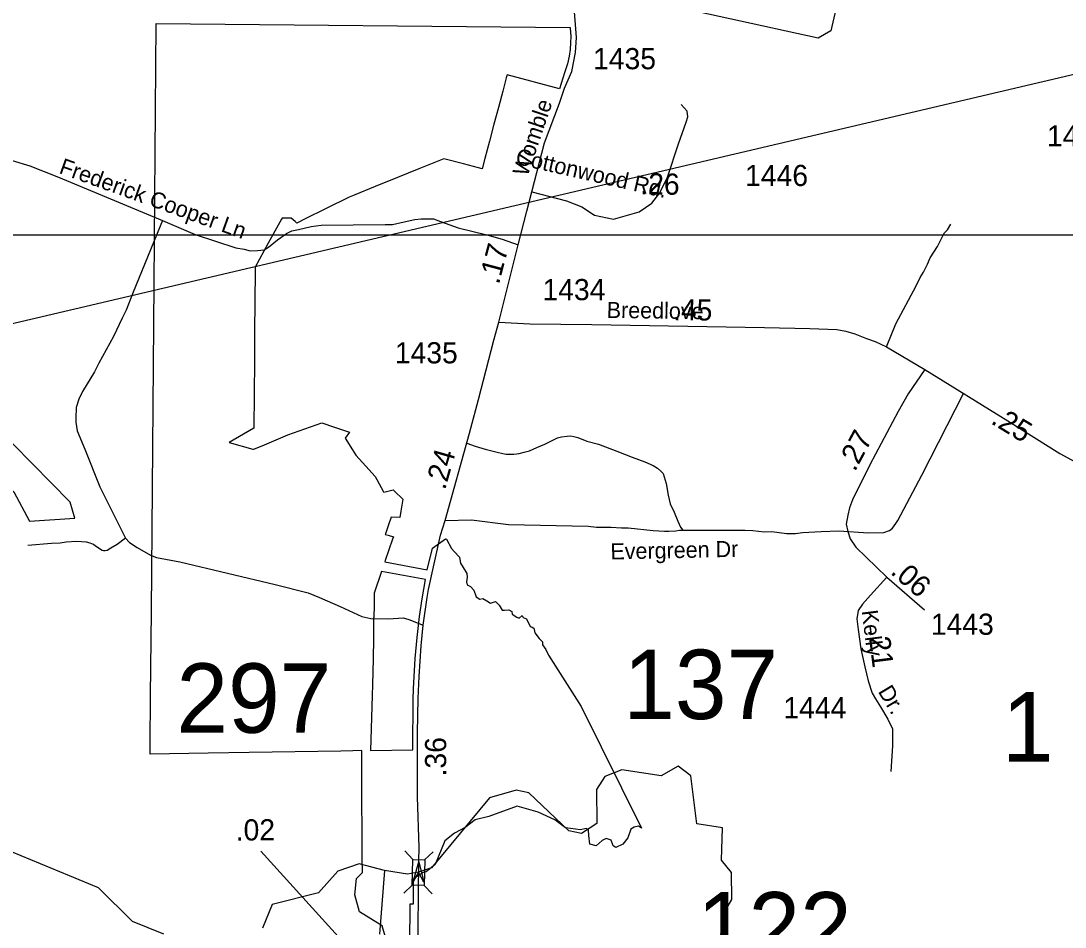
# Model space of a CAD drawing. Extents: x 2220236 to 2384410, y 720751 to 894131.
# Drawn here: x 2304345 to 2310514, y 814069 to 819421 of the extents above; entities that cross this region are included whole.
import ezdxf

# ---------------------------------------------------------------- set-up
doc = ezdxf.new("R2010")
doc.units = 0
for name, color, linetype in [('Exist Boundary Political City Limit New', 7, 'Continuous'), ('Exist Hydrographic Creek Single Shore', 7, 'Continuous'), ('Exist Hydrographic Lake Shore', 7, 'Continuous'), ('Exist Hydrographic Pond Under 1500 Sq Ft', 7, 'Continuous'), ('Exist Road Non-System Type 51', 7, 'Continuous'), ('Exist Road Non-System Type 51 Label', 7, 'Continuous'), ('Exist Road Primary US Mileage Hundredths English Label', 7, 'Continuous'), ('Exist Road Secondary Mileage Hundredths English Label', 7, 'Continuous'), ('Exist Road Secondary Structure Standard Bridge Attributed CELL', 7, 'Continuous'), ('Exist Road Secondary Structure Standard Bridge CELL', 7, 'Continuous'), ('Exist Road Secondary Structure Standard Bridge Number Label', 7, 'Continuous'), ('Exist Road Secondary Type 51 Attributed', 7, 'Continuous'), ('Exist Road Secondary Type 51 Label', 7, 'Continuous'), ('Exist Road Secondary Type 51 Number Label', 7, 'Continuous'), ('Exist Utilities Electrical Transmission Line', 7, 'Continuous'), ('Map Preparation Boundary City Limit Buffer Line', 7, 'Continuous'), ('Map Preparation Inset Cut Line', 7, 'Continuous')]:
    doc.layers.add(name, color=color, linetype=linetype)

msp = doc.modelspace()

# ---------------------------------------------------------------- linework, layer by layer
at = {"layer": 'Exist Boundary Political City Limit New'}
msp.add_lwpolyline([(2306496.2, 814015.8), (2306478.5, 814077.4), (2306345.8, 814158.9), (2306317, 814258.9), (2306327.2, 814356), (2306362.5, 814391.9), (2306362.2, 814474.1), (2306361.8, 814568), (2306360, 814883.1), (2306359.8, 815111.4), (2306305.8, 815110.3), (2306236, 815108.9), (2305694, 815100.2), (2305451.5, 815096.4), (2305107.8, 815090.9), (2305108.2, 815143.5), (2305111, 815434.5), (2305115.8, 815932.7), (2305132, 817870.4), (2305144.8, 819406.5), (2307589, 819382.9), (2307589.8, 819382.9), (2307590, 819379.1), (2307593.5, 819328.9), (2307592.5, 819293.5), (2307590.2, 819252.2), (2307583.5, 819212.9), (2307573.5, 819168.7), (2307557.5, 819114), (2307526.2, 819020.1), (2307217.2, 819102.4), (2307212.5, 819084.4), (2307191.5, 819005.8), (2307165.8, 818909.1), (2307139.5, 818810.6), (2307112.8, 818710.1), (2307086, 818609.6), (2307069.5, 818547.4), (2307048.5, 818553.1), (2306960.8, 818576.4), (2306844.5, 818607.3), (2306696.2, 818547.3), (2306570.5, 818496.4), (2306439, 818443.2), (2306314.2, 818392.7), (2306284.2, 818380.6), (2306145.5, 818311.8), (2306025.2, 818252), (2305975.8, 818227.5), (2305965.2, 818236.1), (2305941, 818255.8), (2305888, 818256.2), (2305885.2, 818251.3), (2305806.5, 818108.2), (2305755, 818014.8), (2305728.5, 817966.8), (2305728.5, 817944.9), (2305727, 817761.8), (2305725.8, 817587.6), (2305724.2, 817412.8), (2305722.8, 817216.5), (2305721.2, 817015.4), (2305574.5, 816931.6), (2305715.2, 816892.9), (2305721.2, 816891.2), (2305785.2, 816918.1), (2305922.2, 816975.9), (2306123.2, 817047.2), (2306198.5, 817021.4), (2306286.2, 816991.4), (2306261, 816956.4), (2306303.2, 816887.6), (2306324.8, 816856.2), (2306382.8, 816792.3), (2306438.2, 816731.1), (2306447.8, 816713.5), (2306487.8, 816639.8), (2306489.2, 816637.1), (2306528.2, 816647.4), (2306545, 816651.8), (2306552.2, 816644.6), (2306601.5, 816595.8), (2306590, 816526.2), (2306583.8, 816488.6), (2306532, 816491.2), (2306516.5, 816445.1), (2306498.5, 816392.1), (2306497.5, 816388.7), (2306514, 816383.8), (2306545.5, 816374.6), (2306540.5, 816360.5), (2306498, 816235.2), (2306495.2, 816226.4), (2306746, 816180.2), (2306776.2, 816306.5), (2306854, 816361.4), (2306859, 816360.2), (2306889.8, 816305.4), (2306905.5, 816287.9), (2306937.2, 816254.8), (2306937.5, 816239.8), (2306941.8, 816218.4), (2306957.8, 816192.4), (2306980.2, 816158), (2306981.2, 816136.6), (2306978.2, 816108.5), (2306981.5, 816089.8), (2307000.8, 816080.6), (2307020.2, 816059.9), (2307034.8, 816020.6), (2307056.8, 816006), (2307074.8, 816009.8), (2307098.8, 815996.4), (2307119, 815982.3), (2307149, 815992.4), (2307169.8, 815970.4), (2307188.2, 815941.4), (2307201.8, 815942), (2307227.8, 815943.1), (2307245.2, 815933.5), (2307248.2, 815916.5), (2307274.2, 815900.4), (2307288.2, 815892.8), (2307307.2, 815909.9), (2307312.5, 815897.9), (2307332, 815890), (2307354, 815845.4), (2307365, 815841.4), (2307376, 815834.1), (2307379, 815817.8), (2307381.2, 815806.2), (2307407, 815772.8), (2307426.2, 815754.8), (2307425.8, 815736.1), (2307446, 815708.4), (2307461.2, 815675.2), (2307655.2, 815371.8), (2308011.8, 814652.9), (2307994.2, 814664.4), (2307968, 814659.3), (2307948.5, 814648.5), (2307930.8, 814596.9), (2307902, 814559.7), (2307860.5, 814539.3), (2307844.5, 814549.1), (2307831.8, 814582.6), (2307802.8, 814593.4), (2307778.8, 814580.3), (2307743.8, 814550.1), (2307706.8, 814559.9), (2307700, 814610.3), (2307698.2, 814643.4), (2307684.8, 814651.2), (2307651.2, 814643.2), (2307562.5, 814655.3), (2307500.5, 814702.5), (2307402, 814748.1), (2307277, 814783.2), (2307109.8, 814721.7), (2307028.2, 814701.9), (2306970.5, 814657.8), (2306907.2, 814624), (2306849.2, 814577.8), (2306792.5, 814438.4), (2306738.8, 814395.9), (2306722.5, 814392.3), (2306662.8, 814353.2), (2306663.2, 814204.9), (2306643.2, 814204.9), (2306643.2, 814119.3), (2306633.8, 813771.7)], dxfattribs=at)
msp.add_lwpolyline([(2306420.5, 815437.1), (2306410.2, 815112.2), (2306659.8, 815116.2), (2306662.5, 815415.6), (2306664, 815475.8), (2306673.8, 815655.4), (2306686.2, 815780), (2306701, 815904.1), (2306714.8, 816007.9), (2306735.2, 816121.6), (2306476, 816169), (2306433, 816041.8), (2306432.8, 816034.6), (2306431.2, 815968.8), (2306429.5, 815899.4), (2306429.2, 815892.9), (2306428.8, 815872.6), (2306428.5, 815774.4), (2306425.5, 815654.4), (2306422, 815500.4)], close=True, dxfattribs=at)
at = {"layer": 'Exist Hydrographic Creek Single Shore'}
for points in [[(2308479.6, 814025), (2308495.6, 814147.1), (2308544.6, 814231.2), (2308542.5, 814391.9), (2308483.5, 814465), (2308489.4, 814655.6), (2308339.5, 814678.9), (2308303.4, 814963), (2308227.5, 815019), (2308128.5, 814962.4), (2307894.5, 814998.8), (2307795.5, 814958.6), (2307746.5, 814881.1), (2307748.5, 814681), (2307657.5, 814621.5), (2307582.4, 814638.1), (2307346.4, 814861.5), (2307271.4, 814878.1), (2307113.5, 814832.3), (2306771.4, 814418.4), (2306694.9, 814392.9), (2306628.2, 814381.9), (2306493.4, 814403.3)], [(2305189.5, 814028.3), (2305005.3, 814102.8), (2304803.3, 814301.4), (2304058.4, 814608.9)], [(2306493.4, 814403.3), (2306343.5, 814443.1), (2306218.4, 814398.6), (2306103.4, 814272.5), (2305829.4, 814202.2), (2305772.4, 814062)], [(2306493.4, 814403.3), (2306464.5, 814027.9)]]:
    msp.add_lwpolyline(points, dxfattribs=at)
at = {"layer": 'Exist Hydrographic Lake Shore'}
msp.add_lwpolyline([(2309185.6, 819603.6), (2309130.4, 819361.8), (2309055.6, 819319.4), (2308012.4, 819549), (2307605.6, 819568.2), (2307220.5, 819615.2), (2307069.4, 819664.8), (2306825.4, 819904.2)], dxfattribs=at)
at = {"layer": 'Exist Hydrographic Pond Under 1500 Sq Ft'}
msp.add_lwpolyline([(2304395.6, 816466.7), (2304662.8, 816484.1), (2304636.8, 816578.2), (2304299.7, 816922.2), (2304106.7, 817012.8), (2303982.6, 816984.7), (2303983.7, 816902.7), (2304302.7, 816640.1), (2304395.6, 816466.7)], dxfattribs=at)
at = {"layer": 'Exist Road Non-System Type 51'}
msp.add_line((2309494.3, 815139), (2309485.5, 814988.4), dxfattribs=at)
for points in [[(2304293, 818596.7), (2304397.1, 818565.7), (2304566.7, 818497.5), (2305182.2, 818243.4)], [(2305182.2, 818243.4), (2305009, 817819.3), (2304966.1, 817712.9), (2304942.6, 817666.6), (2304891.8, 817558.1), (2304805.4, 817399.3), (2304780.1, 817349), (2304709.4, 817232.3), (2304687.8, 817188.2), (2304672.5, 817138), (2304669, 817076), (2304669.4, 817052), (2304677.9, 817000.1), (2304723.1, 816892.6), (2304811.4, 816669.7), (2304962.5, 816365.4)], [(2305182.2, 818243.4), (2305373.8, 818159.3), (2305615.5, 818081.5), (2305664.8, 818073), (2305700, 818063.2), (2305743.6, 818064.6), (2305781.6, 818070.2), (2305808.3, 818084.3), (2305861.8, 818127.9), (2305913.8, 818165.9), (2305946.2, 818181.4), (2305984.2, 818189.9), (2306060.3, 818206.4), (2306118.2, 818215.2), (2306497.7, 818218), (2306539.9, 818218), (2306608.8, 818234.9), (2306672.2, 818249), (2306710.1, 818253.2), (2306745.3, 818253.2), (2306781.9, 818251.8), (2306824.1, 818236.3), (2306928, 818199.8), (2307097.4, 818158.3), (2307188.7, 818132.6), (2307282.1, 818099.1)], [(2309459.3, 817497.2), (2309514.8, 817631.9), (2309634.5, 817857), (2309657.9, 817905.4), (2309677.6, 817937.6), (2309700.9, 817983.8), (2309716.6, 818021.8), (2309759.9, 818088.4), (2309794.8, 818156.7), (2309801, 818168.7), (2309818.9, 818186.9), (2309838.5, 818221.1)], [(2308256.6, 816412.7), (2308624.3, 816412.9), (2308670.4, 816411.4), (2308736.5, 816404.1), (2308781.9, 816405.4), (2308867.7, 816394.2), (2308921.1, 816394.2), (2308963.4, 816399.8), (2309073.3, 816406.4), (2309177.2, 816409.6), (2309353.1, 816397), (2309443.1, 816399.8), (2309476.9, 816411.1), (2309495.2, 816425.1), (2309513.5, 816453.3), (2309526.1, 816471.6), (2309668.2, 816737.7), (2309915.1, 817225.5)], [(2306978.8, 816926.6), (2307028.8, 816909.4), (2307087.9, 816892.5), (2307159.7, 816874.2), (2307192, 816865.8), (2307211.7, 816863), (2307235.6, 816861.6), (2307258.1, 816863), (2307289.1, 816867.2), (2307318.6, 816874.2), (2307349.6, 816882.7), (2307393.2, 816902.4), (2307441, 816922.1), (2307515.6, 816958.7), (2307539.5, 816965.7), (2307571.9, 816968.6), (2307594.4, 816970), (2307611.3, 816967.2), (2307635.2, 816960.1), (2307688.7, 816939), (2307757.6, 816922.1), (2307865.9, 816879.9), (2307956, 816844.7), (2308032, 816817.9), (2308081.2, 816795.4), (2308106.5, 816779.9), (2308126.2, 816761.6), (2308138.9, 816748.9), (2308145.9, 816729.2), (2308157.2, 816689.8), (2308169.8, 816620.8), (2308181.1, 816568.7), (2308205, 816519.5), (2308226.1, 816466), (2308243, 816430.8), (2308256.6, 816412.7)], [(2306851.5, 816471.6), (2307006.3, 816474.4), (2307225.8, 816447.7), (2307696.6, 816436.8), (2307746.4, 816430.8), (2307832.2, 816430.8), (2307894.1, 816426.5), (2307933.5, 816426.5), (2308081.2, 816412.5), (2308147.3, 816406.8), (2308174.1, 816408.2), (2308214.7, 816410.4), (2308236.6, 816412.7), (2308256.6, 816412.7)], [(2304962.5, 816365.4), (2304913, 816328.9), (2304877.3, 816306.5), (2304855.4, 816294.4), (2304843.4, 816292.3), (2304833.4, 816292.1), (2304825.4, 816293.9), (2304785.1, 816319.5), (2304773.1, 816329.4), (2304755, 816337.3), (2304732.9, 816343), (2304673, 816346.3), (2304613, 816341.7), (2304577.1, 816337.2), (2304525.2, 816334.7), (2304385.2, 816323.2)], [(2304962.5, 816365.4), (2304986.8, 816339.7), (2305031.1, 816312.1), (2305111.6, 816265), (2305145.8, 816251.4), (2305284.9, 816227.3), (2305847.1, 816093), (2306041.8, 816042.9), (2306109.4, 816016.2), (2306230.4, 815962.7), (2306282.4, 815938.7), (2306359.8, 815903.5), (2306413.3, 815890.9), (2306518.8, 815889.4), (2306603.2, 815896.5), (2306637, 815885.2), (2306721.4, 815852.6)]]:
    msp.add_lwpolyline(points, dxfattribs=at)
at = {"layer": 'Exist Road Primary US Mileage Hundredths English Label'}
msp.add_line((2306550, 813648.7), (2305763.2, 814518), dxfattribs=at)
at = {"layer": 'Exist Road Secondary Structure Standard Bridge Attributed CELL'}
msp.add_lwpolyline([(2306661.8, 814337), (2306696.7, 814453.8), (2306724.9, 814335.2), (2306694.9, 814392.9)], close=True, dxfattribs=at)
at = {"layer": 'Exist Road Secondary Structure Standard Bridge CELL'}
for p, q in [((2306661.3, 814468.5), (2306613.9, 814518.7)), ((2306730.2, 814466.6), (2306780.4, 814514)), ((2306606.6, 814270.1), (2306656.7, 814317.5)), ((2306774.7, 814265.4), (2306727.3, 814315.5))]:
    msp.add_line(p, q, dxfattribs=at)
msp.add_lwpolyline([(2306656.7, 814317.5), (2306660.9, 814468.5), (2306731.5, 814466.6), (2306727.3, 814315.5)], close=True, dxfattribs=at)
at = {"layer": 'Exist Road Secondary Type 51 Attributed'}
msp.add_line((2309461.4, 816135), (2309683.1, 815942.1), dxfattribs=at)
for points in [[(2307363.3, 818412.5), (2307439.3, 818700.9), (2307526.8, 818935), (2307557.5, 819024.8), (2307599.1, 819123.5), (2307621, 819235.2), (2307627.6, 819322.9), (2307612.2, 819526.7), (2307555.8, 819875.2)], [(2307363.3, 818412.5), (2307568.6, 818357.9), (2307658.3, 818323.6), (2307734.8, 818273.5), (2307845.6, 818249.8), (2307998.7, 818294.6), (2308072.5, 818344.7), (2308120, 818405.4), (2308164.9, 818497.7), (2308230.8, 818695.6), (2308275.7, 818822.3), (2308286.2, 818853.9), (2308280.9, 818888.2), (2308246.6, 818927.8)], [(2307169.5, 817641.5), (2307282.1, 818099.1), (2307334.8, 818298.1), (2307363.3, 818412.5)], [(2306696.3, 814459.1), (2306697.4, 814539), (2306688.2, 814838.7), (2306687.6, 815216.5), (2306691.2, 815418.5), (2306698.2, 815549.5), (2306710.6, 815730.5), (2306721.4, 815852.6), (2306745.3, 816016.2), (2306753.8, 816062.6), (2306824.9, 816383.1), (2306851.5, 816471.6), (2306995, 816985.5), (2307048.5, 817185.4), (2307140, 817535.9), (2307169.5, 817641.5)], [(2307169.5, 817641.5), (2307352.4, 817631.7), (2307718.9, 817628.1), (2308738.9, 817611.2), (2309006.3, 817605.6), (2309165.5, 817598.2), (2309219.5, 817588.8), (2309271.6, 817573.3), (2309341.9, 817546), (2309391.8, 817528.2), (2309459.3, 817497.2), (2309685.8, 817362)], [(2309685.8, 817362), (2309586.7, 817219.6), (2309528.9, 817113.5), (2309360.2, 816800.2), (2309258.9, 816592.9), (2309239.6, 816544.7), (2309230, 816501.3), (2309220.4, 816448.3), (2309230, 816404.9), (2309244.5, 816361.5), (2309278.2, 816313.3), (2309461.4, 816135)], [(2309685.8, 817362), (2310176.9, 817060), (2310482.6, 816867.3), (2310621.6, 816791.1), (2310739.6, 816720.2), (2310772.9, 816698.5), (2310829.7, 816654.3)], [(2309461.4, 816135), (2309365, 816030.4), (2309316.8, 815977.3), (2309292.7, 815938.7), (2309283, 815890.5), (2309292.7, 815827.8), (2309307.1, 815712), (2309331.2, 815605.9), (2309350.5, 815523.9), (2309374.6, 815451.5), (2309393.9, 815417.7), (2309422.8, 815369.5), (2309466.2, 815297.1), (2309495.1, 815239.2), (2309495.1, 815152.4), (2309494.3, 815139)], [(2306666.2, 813531.8), (2306682.7, 813739), (2306691.2, 813938.9), (2306691.2, 814064.2), (2306696.3, 814459.1)]]:
    msp.add_lwpolyline(points, dxfattribs=at)
at = {"layer": 'Exist Utilities Electrical Transmission Line'}
msp.add_lwpolyline([(2295924, 816056.1), (2298361.2, 816772.1), (2303102.7, 817354.9), (2310903.7, 819186.1), (2317962.4, 822463)], dxfattribs=at)
at = {"layer": 'Map Preparation Boundary City Limit Buffer Line'}
msp.add_lwpolyline([(2306496.2, 814015.8), (2306478.5, 814077.4), (2306345.8, 814158.9), (2306317, 814258.9), (2306327.2, 814356), (2306362.5, 814391.9), (2306362.2, 814474.1), (2306361.8, 814568), (2306360, 814883.1), (2306359.8, 815111.4), (2306305.8, 815110.3), (2306236, 815108.9), (2305694, 815100.2), (2305451.5, 815096.4), (2305107.8, 815090.9), (2305108.2, 815143.5), (2305111, 815434.5), (2305115.8, 815932.7), (2305132, 817870.4), (2305144.8, 819406.5), (2307589, 819382.9), (2307589.8, 819382.9), (2307590, 819379.1), (2307593.5, 819328.9), (2307592.5, 819293.5), (2307590.2, 819252.2), (2307583.5, 819212.9), (2307573.5, 819168.7), (2307557.5, 819114), (2307526.2, 819020.1), (2307217.2, 819102.4), (2307212.5, 819084.4), (2307191.5, 819005.8), (2307165.8, 818909.1), (2307139.5, 818810.6), (2307112.8, 818710.1), (2307086, 818609.6), (2307069.5, 818547.4), (2307048.5, 818553.1), (2306960.8, 818576.4), (2306844.5, 818607.3), (2306696.2, 818547.3), (2306570.5, 818496.4), (2306439, 818443.2), (2306314.2, 818392.7), (2306284.2, 818380.6), (2306145.5, 818311.8), (2306025.2, 818252), (2305975.8, 818227.5), (2305965.2, 818236.1), (2305941, 818255.8), (2305888, 818256.2), (2305885.2, 818251.3), (2305806.5, 818108.2), (2305755, 818014.8), (2305728.5, 817966.8), (2305728.5, 817944.9), (2305727, 817761.8), (2305725.8, 817587.6), (2305724.2, 817412.8), (2305722.8, 817216.5), (2305721.2, 817015.4), (2305574.5, 816931.6), (2305715.2, 816892.9), (2305721.2, 816891.2), (2305785.2, 816918.1), (2305922.2, 816975.9), (2306123.2, 817047.2), (2306198.5, 817021.4), (2306286.2, 816991.4), (2306261, 816956.4), (2306303.2, 816887.6), (2306324.8, 816856.2), (2306382.8, 816792.3), (2306438.2, 816731.1), (2306447.8, 816713.5), (2306487.8, 816639.8), (2306489.2, 816637.1), (2306528.2, 816647.4), (2306545, 816651.8), (2306552.2, 816644.6), (2306601.5, 816595.8), (2306590, 816526.2), (2306583.8, 816488.6), (2306532, 816491.2), (2306516.5, 816445.1), (2306498.5, 816392.1), (2306497.5, 816388.7), (2306514, 816383.8), (2306545.5, 816374.6), (2306540.5, 816360.5), (2306498, 816235.2), (2306495.2, 816226.4), (2306746, 816180.2), (2306776.2, 816306.5), (2306854, 816361.4), (2306859, 816360.2), (2306889.8, 816305.4), (2306905.5, 816287.9), (2306937.2, 816254.8), (2306937.5, 816239.8), (2306941.8, 816218.4), (2306957.8, 816192.4), (2306980.2, 816158), (2306981.2, 816136.6), (2306978.2, 816108.5), (2306981.5, 816089.8), (2307000.8, 816080.6), (2307020.2, 816059.9), (2307034.8, 816020.6), (2307056.8, 816006), (2307074.8, 816009.8), (2307098.8, 815996.4), (2307119, 815982.3), (2307149, 815992.4), (2307169.8, 815970.4), (2307188.2, 815941.4), (2307201.8, 815942), (2307227.8, 815943.1), (2307245.2, 815933.5), (2307248.2, 815916.5), (2307274.2, 815900.4), (2307288.2, 815892.8), (2307307.2, 815909.9), (2307312.5, 815897.9), (2307332, 815890), (2307354, 815845.4), (2307365, 815841.4), (2307376, 815834.1), (2307379, 815817.8), (2307381.2, 815806.2), (2307407, 815772.8), (2307426.2, 815754.8), (2307425.8, 815736.1), (2307446, 815708.4), (2307461.2, 815675.2), (2307655.2, 815371.8), (2308011.8, 814652.9), (2307994.2, 814664.4), (2307968, 814659.3), (2307948.5, 814648.5), (2307930.8, 814596.9), (2307902, 814559.7), (2307860.5, 814539.3), (2307844.5, 814549.1), (2307831.8, 814582.6), (2307802.8, 814593.4), (2307778.8, 814580.3), (2307743.8, 814550.1), (2307706.8, 814559.9), (2307700, 814610.3), (2307698.2, 814643.4), (2307684.8, 814651.2), (2307651.2, 814643.2), (2307562.5, 814655.3), (2307500.5, 814702.5), (2307402, 814748.1), (2307277, 814783.2), (2307109.8, 814721.7), (2307028.2, 814701.9), (2306970.5, 814657.8), (2306907.2, 814624), (2306849.2, 814577.8), (2306792.5, 814438.4), (2306738.8, 814395.9), (2306722.5, 814392.3), (2306662.8, 814353.2), (2306663.2, 814204.9), (2306643.2, 814204.9), (2306643.2, 814119.3), (2306633.8, 813771.7)], dxfattribs=at)
msp.add_lwpolyline([(2306420.5, 815437.1), (2306410.2, 815112.2), (2306659.8, 815116.2), (2306662.5, 815415.6), (2306664, 815475.8), (2306673.8, 815655.4), (2306686.2, 815780), (2306701, 815904.1), (2306714.8, 816007.9), (2306735.2, 816121.6), (2306476, 816169), (2306433, 816041.8), (2306432.8, 816034.6), (2306431.2, 815968.8), (2306429.5, 815899.4), (2306429.2, 815892.9), (2306428.8, 815872.6), (2306428.5, 815774.4), (2306425.5, 815654.4), (2306422, 815500.4)], close=True, dxfattribs=at)
at = {"layer": 'Map Preparation Inset Cut Line'}
msp.add_lwpolyline([(2299633.7, 818158.8), (2318694.1, 818158.8), (2318694.1, 801601.3), (2299633.7, 801601.3), (2299633.7, 818158.8)], dxfattribs=at)
msp.add_lwpolyline([(2299633.7, 818158.8), (2318694.1, 818158.8), (2318694.1, 801601.3), (2299633.7, 801601.3), (2299633.7, 818158.8)], dxfattribs=at)

# ---------------------------------------------------------------- texts
at = {"layer": 'Exist Road Non-System Type 51 Label'}
for s, rotation, p in [('Frederick Cooper Ln', 340.24626, (2304565, 818523.4)), ('Evergreen Dr', 1.22686, (2307828.9, 816240.2))]:
    msp.add_text(s, height=95, rotation=rotation, dxfattribs=at).set_placement(p)
at = {"layer": 'Exist Road Primary US Mileage Hundredths English Label'}
msp.add_text('.02', height=125, rotation=0.43103, dxfattribs=at).set_placement((2305614.7, 814580.1))
at = {"layer": 'Exist Road Secondary Mileage Hundredths English Label'}
for s, rotation, p in [('.26', 358.98483, (2308003.6, 818398.1)), ('.17', 75.16172, (2307168.7, 817860.8)), ('.45', 359.27175, (2308197.4, 817654.1)), ('.25', 328.66209, (2310070, 817046.8)), ('.27', 61.69923, (2309271.9, 816754.6)), ('.24', 74.10641, (2306850.8, 816646.8)), ('.06', 318.99094, (2309477, 816160.5)), ('.21', 277.11957, (2309349.5, 815826.4)), ('.36', 90.073, (2306857.8, 814959))]:
    msp.add_text(s, height=125, rotation=rotation, dxfattribs=at).set_placement(p)
at = {"layer": 'Exist Road Secondary Structure Standard Bridge Number Label'}
for s, p in [('137', (2307903.8, 815297.7)), ('297', (2305264.3, 815216.7)), ('1', (2310141.4, 815047.1)), ('122', (2308339, 813865.8))]:
    msp.add_text(s, height=410.1, dxfattribs=at).set_placement(p)
at = {"layer": 'Exist Road Secondary Type 51 Label'}
for s, rotation, p in [('Womble', 71.36008, (2307337.8, 818497.9)), ('Cottonwood Rd.', 347.14432, (2307262.3, 818577.4)), ('Breedlove', 359.27175, (2307805.7, 817667)), ('Kelly', 277.11957, (2309312.1, 815937)), ('Dr.', 300.94475, (2309406.1, 815461.3))]:
    msp.add_text(s, height=95, rotation=rotation, dxfattribs=at).set_placement(p)
at = {"layer": 'Exist Road Secondary Type 51 Number Label'}
for s, p in [('1435', (2307725.6, 819135.9)), ('1450', (2310407.3, 818679.8)), ('1446', (2308623.8, 818446.1)), ('1434', (2307426.6, 817771.8)), ('1435', (2306554.3, 817398.6)), ('1443', (2309721.2, 815795.5)), ('1444', (2308850.1, 815302.4))]:
    msp.add_text(s, height=125, dxfattribs=at).set_placement(p)

doc.saveas('drawing.dxf')
